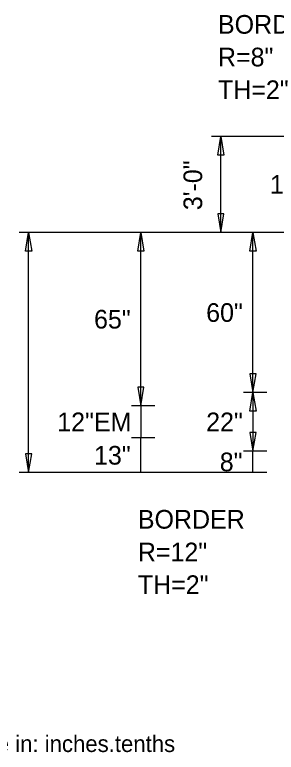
# Model space of a CAD drawing. Extents: x 2149961 to 2150220, y 145114 to 145240.
# Drawn here: x 2150023.21 to 2150031.37, y 145138.4 to 145161.43 of the extents above; entities that cross this region are included whole.
import ezdxf

# ---------------------------------------------------------------- set-up
doc = ezdxf.new("R2010")
doc.units = 0
doc.layers.add('GSDIMS', color=7, linetype='Continuous')
doc.layers.add('Level 1', color=7, linetype='Continuous')

msp = doc.modelspace()

# ---------------------------------------------------------------- linework, layer by layer
at = {"layer": 'GSDIMS'}
for p, q in [((2150030.082, 145157.634), (2150029.353, 145157.634)), ((2150029.645, 145154.633), (2150029.645, 145157.634)), ((2150033.582, 145157.634), (2150030.082, 145157.634)), ((2150024.083, 145154.633), (2150023.353, 145154.633)), ((2150023.645, 145147.133), (2150023.645, 145154.633)), ((2150031.083, 145154.633), (2150024.083, 145154.633)), ((2150027.583, 145154.633), (2150026.853, 145154.633)), ((2150027.145, 145149.216), (2150027.145, 145154.633)), ((2150030.082, 145154.633), (2150029.353, 145154.633)), ((2150033.582, 145154.633), (2150030.082, 145154.633)), ((2150031.083, 145154.633), (2150030.353, 145154.633)), ((2150030.645, 145149.632), (2150030.645, 145154.633)), ((2150031.083, 145149.632), (2150030.353, 145149.632)), ((2150031.083, 145149.632), (2150030.353, 145149.632)), ((2150030.645, 145149.632), (2150030.645, 145147.801)), ((2150027.583, 145149.216), (2150026.853, 145149.216)), ((2150027.583, 145149.216), (2150026.853, 145149.216)), ((2150027.145, 145149.216), (2150027.145, 145148.216)), ((2150027.583, 145148.216), (2150026.853, 145148.216)), ((2150027.583, 145148.216), (2150026.853, 145148.216)), ((2150027.145, 145147.133), (2150027.145, 145148.216)), ((2150031.083, 145147.801), (2150030.353, 145147.801)), ((2150031.083, 145147.801), (2150030.353, 145147.801)), ((2150030.645, 145147.133), (2150030.645, 145147.801)), ((2150024.083, 145147.133), (2150023.353, 145147.133)), ((2150031.083, 145147.133), (2150024.083, 145147.133)), ((2150027.583, 145147.133), (2150026.853, 145147.133)), ((2150031.083, 145147.133), (2150030.353, 145147.133))]:
    msp.add_line(p, q, dxfattribs=at)
for points in [[(2150029.645, 145157.634), (2150029.742, 145157.05), (2150029.547, 145157.05)], [(2150029.645, 145154.633), (2150029.742, 145155.216), (2150029.547, 145155.216)], [(2150023.645, 145154.633), (2150023.742, 145154.05), (2150023.548, 145154.05)], [(2150027.145, 145154.633), (2150027.242, 145154.05), (2150027.048, 145154.05)], [(2150030.645, 145154.633), (2150030.742, 145154.05), (2150030.548, 145154.05)], [(2150030.645, 145149.632), (2150030.742, 145150.215), (2150030.548, 145150.215)], [(2150027.145, 145149.216), (2150027.242, 145149.8), (2150027.048, 145149.8)], [(2150030.645, 145149.632), (2150030.742, 145149.048), (2150030.548, 145149.048)], [(2150030.645, 145147.801), (2150030.742, 145148.385), (2150030.548, 145148.385)], [(2150023.645, 145147.133), (2150023.742, 145147.716), (2150023.548, 145147.716)]]:
    msp.add_lwpolyline(points, close=True, dxfattribs=at)

# ---------------------------------------------------------------- texts
for s, p in [('BORDER', (2150029.554, 145160.842)), ('R=8"', (2150029.554, 145159.821)), ('TH=2"', (2150029.554, 145158.8)), ('12"E', (2150031.175, 145155.842)), ('60"', (2150029.186, 145151.841)), ('65"', (2150025.686, 145151.633)), ('12"EM', (2150024.538, 145148.425)), ('22"', (2150029.186, 145148.425)), ('13"', (2150025.686, 145147.383)), ('8"', (2150029.61, 145147.175)), ('BORDER', (2150027.054, 145145.383)), ('R=12"', (2150027.054, 145144.362)), ('TH=2"', (2150027.054, 145143.341))]:
    msp.add_text(s, height=0.5833, dxfattribs=at).set_placement(p)
msp.add_text('3\'-0"', height=0.5833, rotation=90, dxfattribs=at).set_placement((2150029.061, 145155.331))
at = {"layer": 'Level 1'}
msp.add_text('Dimensions are in: inches.tenths', height=0.51652, dxfattribs=at).set_placement((2150018.235, 145138.406))

doc.saveas('drawing.dxf')
